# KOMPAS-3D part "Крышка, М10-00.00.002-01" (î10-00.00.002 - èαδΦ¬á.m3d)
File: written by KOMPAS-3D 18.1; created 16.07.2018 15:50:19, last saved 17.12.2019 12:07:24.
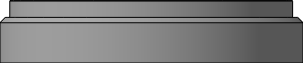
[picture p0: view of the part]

Document properties: Автор: Милов; Полное имя файла: D:\Magna\Магна Ins\Магна ins 10\М10-00.00.000\3Д\М10-00.00.002 - Крышка.m3d

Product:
- Part/product: Крышка  | designation М10-00.00.002-01
    Материал: Полипропилен  ГОСТ 26996-86 (density 900 kg/m3)
    Масса: 0.345988
    Раздел спецификации: Детали
    Форматы листов документа: 2xA4
    Примечание: @100~)2xA4
    source file: М10-00.00.002 - Крышка.cdw
- Part/product: Крышка ПВХ  | designation М13-01.00.002
    Материал: Полипропилен  ГОСТ 26996-86 (density 900 kg/m3)
    Масса: 0.324102
    Раздел спецификации: Детали
    Форматы листов документа: 2xA4См. заказ
    Примечание: @100~)2xA4См. заказ
- Part/product: Крышка  | designation М10-00.00.002
    Материал: Полипропилен  ГОСТ 26996-86 (density 900 kg/m3)
    Масса: 0.324102
    Раздел спецификации: Детали
    Форматы листов документа: 4xA4
    Примечание: @100~)4xA4
    source file: М10-00.00.002 - Крышка.cdw
- Part/product: Крышка  | designation М24-00.00.002-02
    Материал: Полипропилен  ГОСТ 26996-86 (density 900 kg/m3)
    Масса: 0.284697
    Раздел спецификации: Детали
    Форматы листов документа: 2xA4
    Примечание: @100~)2xA4

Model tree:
1. Эскиз:1
2. Операция вращения:1
     Угол 1 = 360
3. Фаска:1  (with: Операция вращения:1)
     Угол = 45; Длина 1 = 2.5; Длина 2 = 2.5
4. Эскиз:2  (with: Операция вращения:1)
5. Отверстие:1
     Глубина выреза = 10; Диаметр отверстия = 8; Угол конуса торца = 118; Координата Y = 57.5
6. Массив по концентрической сетке:1  (with: Отверстие:1, Эскиз:2)  (4 pattern instances)
     Шаг 2 = 360
7. Условное изображение резьбы:1  (with: Операция вращения:1, Фаска:1)  (labels: M140x3; cil0_24705-2004 fine)
     Шаг резьбы = 3; Номинальный диаметр резьбы = 140
8. Подгонка:1  (with: Фаска:1, Операция вращения:1)
9. Фаска:2  (with: Операция вращения:1)
     Угол = 45; Длина 1 = 0.5; Длина 2 = 0.5
10. Скругление:1  (with: Операция вращения:1)
     Радиус = 1
11. Скругление:2  (with: Операция вращения:1)  (labels: Полипропилен  ГОСТ 26996-86)
     Радиус = 5
12. Эскиз:4  (with: Операция вращения:1)
13. Элемент выдавливания:1
     Расстояние 2 = 20
14. Эскиз:5  (with: Элемент выдавливания:1)
15. Элемент выдавливания:2
     Расстояние 1 = 4
16. Фаска:3  (with: Элемент выдавливания:1)
     Угол = 45; Длина 1 = 2.5; Длина 2 = 2.5
17. Условное изображение резьбы:2  (with: Элемент выдавливания:1, Элемент выдавливания:2, Фаска:3)  (labels: M75x3; cil0_24705-2004 fine)
     Длина резьбы = 15.1238; Шаг резьбы = 3; Номинальный диаметр резьбы = 75
18. Подгонка:1  (with: Фаска:3, Элемент выдавливания:1)
19. Эскиз:7
20. Элемент вращения:1
     Угол 1 = 360
21. Скругление:3  (with: Элемент вращения:1)
     Радиус = 0.2
22. Ось конической поверхности:33  (with: Операция вращения:1)
23. Смещенная плоскость:58  (with: Элемент выдавливания:1)
24. ЛСК:33
25. Эскиз:10
26. Присоединительная точка:3
     Перенос X = -1.3; Расстояние = -1.3
27. Элемент вращения:4
     Угол 1 = 360
28. Канавка для торцовых уплотнений внутренние 58x64x3,6 ГОСТ 9833-73  (labels: Полипропилен  ГОСТ 26996-86; М10-00.00.002-01 - Крышка с кольцом.a3d)
29. Эскиз:12  (with: Операция вращения:1, Фаска:3)
30. Элемент выдавливания:3
     Расстояние 2 = 6
31. Фаска:4  (with: Элемент выдавливания:3)  (labels: Полипропилен  ГОСТ 26996-86)
     Угол = 45; Длина 1 = 2.5; Длина 2 = 2.5

Expressions: 115/2; 21+6
Referenced files in D:\Magna\Магна Ins\Магна ins 10\М10-00.00.000\3Д\: М10-00.00.002-01 - Крышка с кольцом.a3d
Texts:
  Body Specification ( left align )
  Body Specificaton ( centered )
  KTE.LIST=wwIk1qzymX7tHzGZ5WC09d
  Edge1
  Edge2
  Линейный размер с обрывом
  Крышка с кольцом

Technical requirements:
  Gost Type A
